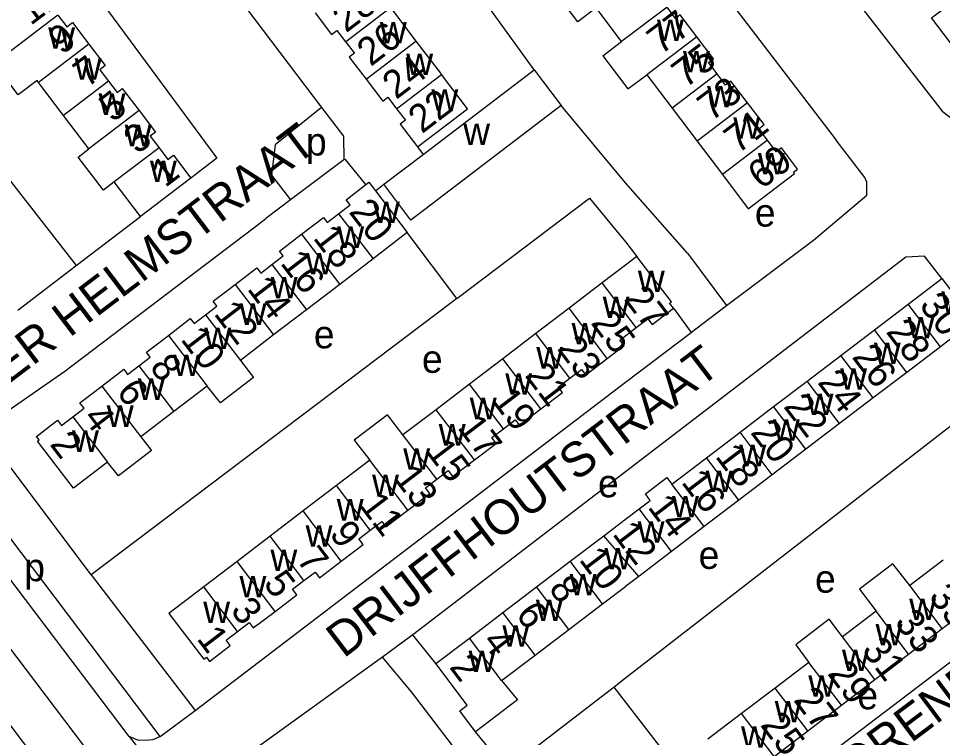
# Model space of a CAD drawing. Extents: x 159294 to 161936, y 384538 to 386517.
# Drawn here: x 160412.8 to 160545.6, y 385575.5 to 385678.8 of the extents above; entities that cross this region are included whole.
import ezdxf

# ---------------------------------------------------------------- set-up
doc = ezdxf.new("R2010")
doc.units = 0
for name, color, linetype in [('BLT_Basislijn', 7, 'Continuous'), ('BLT_Bebouwing', 7, 'Continuous'), ('BLT_Centroide', 7, 'Continuous'), ('BLT_Huisnummer', 7, 'Continuous'), ('BLT_Huisnummer_ tussenligend', 7, 'Continuous'), ('BLT_Onderverdeling_panden', 7, 'Continuous'), ('BLT_Straatnaam', 7, 'Continuous'), ('BLT_Vlakafsluiter', 7, 'Continuous')]:
    doc.layers.add(name, color=color, linetype=linetype)

msp = doc.modelspace()

# ---------------------------------------------------------------- linework, layer by layer
at = {"layer": 'BLT_Basislijn'}
for p, q in [((160425.66, 385706.42), (160456.33, 385665.99)), ((160456.33, 385665.99), (160449.66, 385660.64)), ((160456.33, 385665.99), (160459.45, 385661.88)), ((160459.45, 385661.88), (160459.52, 385658.49)), ((160449.66, 385660.64), (160449.14, 385656.27)), ((160470.09, 385660.36), (160470.9, 385659.26)), ((160459.52, 385658.49), (160451.85, 385652.72)), ((160449.14, 385656.27), (160451.85, 385652.72)), ((160464.06, 385654.02), (160465.25, 385654.97)), ((160451.85, 385652.72), (160448.33, 385650.06)), ((160421.03, 385643.28), (160430.29, 385650.34)), ((160447.84, 385649.69), (160448.33, 385650.06)), ((160475.77, 385638.54), (160468.64, 385648.03)), ((160508.93, 385645.07), (160514.52, 385637.54)), ((160412.66, 385636.9), (160421.03, 385643.28)), ((160506.88, 385637.17), (160509.42, 385633.69)), ((160423.19, 385598.85), (160407.45, 385619.83)), ((160433.13, 385575.64), (160402.33, 385616.36)), ((160428.69, 385575.65), (160400.48, 385612.84)), ((160423.91, 385572.02), (160395.7, 385609.21)), ((160390.64, 385604.74), (160419.63, 385566.66)), ((160423.19, 385598.85), (160438.16, 385579.37)), ((160472.72, 385586.11), (160469.45, 385590.25)), ((160433.13, 385575.64), (160438.16, 385579.37))]:
    msp.add_line(p, q, dxfattribs=at)
for points in [[(160462.6, 385750.62), (160463.37, 385749.24), (160463.73, 385747.8), (160463.54, 385747.15), (160461.25, 385744.68), (160407.86, 385704.37), (160408.02, 385703.72), (160410.79, 385700), (160441.27, 385658.72), (160437.54, 385655.86)], [(160466.65, 385733.68), (160471.23, 385737.23), (160472.38, 385736.43), (160500.69, 385700), (160530.29, 385661.32)], [(160486.88, 385671.4), (160466.25, 385700), (160449.95, 385721.54)], [(160532.44, 385682.31), (160545.5, 385665.46), (160547.76, 385663.73), (160550.07, 385663.68), (160551.02, 385664.1), (160586.59, 385691.5), (160587.15, 385692.07)], [(160381.69, 385691.15), (160383.6, 385688.37), (160385.51, 385688.77), (160385.83, 385688.45), (160421.03, 385643.28)], [(160508.93, 385645.07), (160500, 385655.15), (160490.78, 385666.26)], [(160514.52, 385637.54), (160527, 385646.95), (160534.71, 385653.39), (160534.71, 385655.29), (160534.39, 385655.93), (160530.29, 385661.32)], [(160462.68, 385654.92), (160459.77, 385658.53), (160459.52, 385658.49)], [(160475.77, 385638.54), (160494.85, 385652.96), (160500, 385646.71), (160501.64, 385644.58)], [(160407.45, 385619.83), (160419.41, 385628.13), (160447.84, 385649.69)], [(160545.48, 385641.41), (160542.98, 385644.64), (160540.27, 385644.48), (160500, 385613.68), (160469.45, 385590.25)], [(160475.77, 385638.54), (160475.15, 385638.07), (160423.19, 385598.85)], [(160509.42, 385633.69), (160510.12, 385634.22), (160514.52, 385637.54)], [(160438.16, 385579.37), (160500, 385626.56), (160509.42, 385633.69)], [(160556.46, 385627.73), (160500, 385584), (160498.36, 385582.75)], [(160514.51, 385561.88), (160570.33, 385604.31), (160571.73, 385605.92), (160569.69, 385609.54)], [(160469.45, 385590.25), (160469.12, 385589.99), (160465.07, 385587.05)], [(160465.07, 385587.05), (160464.06, 385586.32), (160443.62, 385571.57)], [(160487.23, 385558.55), (160469.23, 385582.04), (160465.07, 385587.05)], [(160498.36, 385582.75), (160484.46, 385572.06), (160483.32, 385571.65), (160482.22, 385571.7), (160478.46, 385576.33)], [(160507.02, 385571.58), (160500, 385580.61), (160498.36, 385582.75)], [(160433.13, 385575.64), (160432.05, 385575.17), (160430.97, 385575.08), (160429.93, 385575.1), (160428.69, 385575.65)]]:
    msp.add_lwpolyline(points, dxfattribs=at)
at = {"layer": 'BLT_Bebouwing'}
for p, q in [((160466.23, 385680.34), (160469.89, 385675.53)), ((160499.45, 385675.46), (160495.77, 385680.32)), ((160469.89, 385675.53), (160473.55, 385670.72)), ((160496.76, 385673.42), (160499.45, 385675.46)), ((160470.9, 385659.26), (160486.88, 385671.4)), ((160486.88, 385671.4), (160490.78, 385666.26)), ((160419.23, 385664.86), (160415.64, 385669.59)), ((160503.07, 385670.69), (160506.69, 385665.92)), ((160506.69, 385665.92), (160510.29, 385661.17)), ((160422.89, 385660.06), (160419.23, 385664.86)), ((160510.29, 385661.17), (160513.92, 385656.38)), ((160465.25, 385654.97), (160470.9, 385659.26)), ((160513.92, 385656.38), (160517.65, 385651.46)), ((160430.29, 385650.34), (160426.52, 385655.3)), ((160437.54, 385655.86), (160430.29, 385650.34)), ((160464.06, 385654.02), (160468.64, 385648.03)), ((160468.64, 385648.03), (160463.73, 385644.27)), ((160463.73, 385644.27), (160458.93, 385640.59)), ((160501.64, 385644.58), (160500, 385643.33)), ((160500, 385643.33), (160496.66, 385640.79)), ((160458.93, 385640.59), (160454.16, 385636.94)), ((160496.66, 385640.79), (160491.89, 385637.15)), ((160540.63, 385637.73), (160545.48, 385641.41)), ((160545.48, 385641.41), (160550.12, 385635.3)), ((160535.79, 385634.05), (160540.63, 385637.73)), ((160454.16, 385636.94), (160449.43, 385633.32)), ((160491.89, 385637.15), (160487.12, 385633.52)), ((160499.17, 385632.56), (160501.55, 385634.37)), ((160530.96, 385630.38), (160535.79, 385634.05)), ((160449.43, 385633.32), (160444.65, 385629.66)), ((160487.12, 385633.52), (160482.37, 385629.9)), ((160545.27, 385631.62), (160540.44, 385627.95)), ((160482.37, 385629.9), (160477.59, 385626.26)), ((160526.12, 385626.7), (160530.96, 385630.38)), ((160540.44, 385627.95), (160535.6, 385624.27)), ((160439.87, 385625.99), (160435.1, 385622.34)), ((160477.59, 385626.26), (160472.77, 385622.59)), ((160521.29, 385623.03), (160526.12, 385626.7)), ((160516.46, 385619.35), (160521.29, 385623.03)), ((160535.6, 385624.27), (160530.77, 385620.6)), ((160435.1, 385622.34), (160430.33, 385618.69)), ((160472.77, 385622.59), (160468.02, 385618.97)), ((160530.77, 385620.6), (160525.93, 385616.92)), ((160511.62, 385615.68), (160516.46, 385619.35)), ((160525.93, 385616.92), (160521.1, 385613.24)), ((160463.24, 385615.33), (160458.46, 385611.68)), ((160506.65, 385611.89), (160511.62, 385615.68)), ((160521.1, 385613.24), (160516.27, 385609.57)), ((160458.46, 385611.68), (160453.67, 385608.04)), ((160516.27, 385609.57), (160511.33, 385605.82)), ((160453.67, 385608.04), (160448.92, 385604.41)), ((160500, 385606.84), (160501.95, 385608.33)), ((160496.9, 385604.48), (160500, 385606.84)), ((160511.33, 385605.82), (160506.6, 385602.22)), ((160448.92, 385604.41), (160444.17, 385600.8)), ((160492.06, 385600.81), (160496.9, 385604.48)), ((160506.6, 385602.22), (160501.9, 385598.65)), ((160444.17, 385600.8), (160439.38, 385597.15)), ((160487.23, 385597.13), (160492.06, 385600.81)), ((160545.68, 385600.99), (160540.85, 385597.31)), ((160501.9, 385598.65), (160500, 385597.21)), ((160482.39, 385593.46), (160487.23, 385597.13)), ((160496.71, 385594.7), (160500, 385597.21)), ((160491.87, 385591.03), (160496.71, 385594.7)), ((160545.53, 385591.16), (160550.36, 385594.84)), ((160477.56, 385589.78), (160482.39, 385593.46)), ((160536.02, 385593.64), (160531.18, 385589.96)), ((160540.69, 385587.49), (160545.53, 385591.16)), ((160472.72, 385586.11), (160477.56, 385589.78)), ((160487.04, 385587.35), (160491.87, 385591.03)), ((160482.2, 385583.67), (160487.04, 385587.35)), ((160535.86, 385583.81), (160540.69, 385587.49)), ((160526.35, 385586.28), (160521.52, 385582.61)), ((160531.03, 385580.13), (160535.86, 385583.81)), ((160521.52, 385582.61), (160516.68, 385578.93)), ((160526.19, 385576.46), (160531.03, 385580.13)), ((160516.68, 385578.93), (160511.85, 385575.25)), ((160521.36, 385572.78), (160526.19, 385576.46))]:
    msp.add_line(p, q, dxfattribs=at)
for points in [[(160495.77, 385680.32), (160493.17, 385678.28), (160489.54, 385683.06), (160492.15, 385685.1)], [(160555.32, 385673.96), (160550.49, 385670.3), (160545.8, 385676.48), (160543.98, 385678.89), (160548.94, 385682.64), (160550.64, 385680.15)], [(160510.27, 385676.15), (160507.87, 385679.3), (160507.2, 385678.8), (160505.98, 385680.41)], [(160418.42, 385679.28), (160419.72, 385677.58), (160420.52, 385678.19), (160422.88, 385675.1)], [(160455.38, 385679.58), (160457.74, 385676.47), (160458.53, 385677.07), (160459.78, 385675.42)], [(160513.16, 385670.82), (160511.94, 385672.44), (160512.66, 385672.99), (160510.27, 385676.15)], [(160422.88, 385675.1), (160425.23, 385672.01), (160424.45, 385671.41), (160425.69, 385669.78)], [(160459.78, 385675.42), (160461.03, 385673.78), (160460.3, 385673.23), (160462.71, 385670.07)], [(160415.64, 385669.59), (160415.43, 385669.86), (160412.72, 385667.8), (160409.27, 385672.32)], [(160496.76, 385673.42), (160500.36, 385668.67), (160503.07, 385670.69)], [(160517.54, 385666.66), (160515.16, 385669.8), (160514.38, 385669.21), (160513.16, 385670.82)], [(160425.69, 385669.78), (160426.93, 385668.15), (160427.68, 385668.72), (160430.09, 385665.55)], [(160462.71, 385670.07), (160465.12, 385666.91), (160465.84, 385667.46), (160467.1, 385665.81)], [(160470.09, 385660.36), (160474.07, 385663.38), (160477.28, 385665.82), (160473.55, 385670.72)], [(160430.09, 385665.55), (160432.44, 385662.46), (160431.68, 385661.88), (160432.96, 385660.2)], [(160490.78, 385666.26), (160469.15, 385649.83), (160465.25, 385654.97)], [(160467.1, 385665.81), (160468.36, 385664.16), (160467.62, 385663.6), (160470.09, 385660.36)], [(160520.4, 385661.3), (160519.15, 385662.95), (160519.92, 385663.53), (160517.54, 385666.66)], [(160432.96, 385660.2), (160434.24, 385658.52), (160435.04, 385659.13), (160437.54, 385655.86)], [(160524.74, 385657.14), (160522.41, 385660.22), (160521.65, 385659.65), (160520.4, 385661.3)], [(160426.52, 385655.3), (160424.97, 385654.11), (160421.34, 385658.88), (160422.89, 385660.06)], [(160517.65, 385651.46), (160524.3, 385656.5), (160524.16, 385656.69), (160524.74, 385657.14)], [(160458.77, 385650.74), (160460.41, 385651.99), (160459.84, 385652.74), (160462.68, 385654.92)], [(160462.68, 385654.92), (160463.12, 385655.25), (160464.06, 385654.02)], [(160453.42, 385647.79), (160456.58, 385650.21), (160457.14, 385649.49), (160458.77, 385650.74)], [(160449.19, 385643.44), (160450.8, 385644.67), (160450.26, 385645.37), (160453.42, 385647.79)], [(160506.88, 385637.17), (160506.35, 385637.87), (160506.6, 385638.06), (160501.64, 385644.58)], [(160443.88, 385640.55), (160447.01, 385642.95), (160447.58, 385642.21), (160449.19, 385643.44)], [(160439.64, 385636.21), (160441.28, 385637.47), (160440.75, 385638.16), (160443.88, 385640.55)], [(160501.55, 385634.37), (160503.23, 385635.64), (160503.84, 385634.84), (160506.88, 385637.17)], [(160434.3, 385633.26), (160437.44, 385635.67), (160437.99, 385634.95), (160439.64, 385636.21)], [(160550.12, 385635.3), (160546.14, 385632.28), (160545.27, 385631.62)], [(160430.07, 385628.9), (160431.7, 385630.15), (160431.16, 385630.85), (160434.3, 385633.26)], [(160497.38, 385629.95), (160499.8, 385631.79), (160499.17, 385632.56)], [(160444.65, 385629.66), (160446.54, 385627.21), (160441.78, 385623.56), (160439.87, 385625.99)], [(160492, 385627.11), (160493.67, 385628.38), (160494.28, 385627.58), (160497.38, 385629.95)], [(160424.74, 385625.99), (160427.88, 385628.4), (160428.45, 385627.65), (160430.07, 385628.9)], [(160487.85, 385622.71), (160490.93, 385625.06), (160490.34, 385625.84), (160492, 385627.11)], [(160420.58, 385621.55), (160422.2, 385622.8), (160421.6, 385623.59), (160424.74, 385625.99)], [(160468.02, 385618.97), (160465.79, 385621.85), (160461.02, 385618.21), (160463.24, 385615.33)], [(160482.46, 385619.86), (160484.16, 385621.15), (160484.76, 385620.36), (160487.85, 385622.71)], [(160425.56, 385615.04), (160420.68, 385611.3), (160415.49, 385618.07), (160415.72, 385618.24), (160415.33, 385618.76), (160418.37, 385621.08), (160418.95, 385620.31), (160420.58, 385621.55)], [(160478.28, 385615.37), (160481.4, 385617.74), (160480.77, 385618.57), (160482.46, 385619.86)], [(160430.33, 385618.69), (160431.9, 385616.72), (160427.14, 385613.07), (160425.56, 385615.04)], [(160472.89, 385612.59), (160474.52, 385613.83), (160475.16, 385612.99), (160478.28, 385615.37)], [(160468.71, 385608.15), (160471.86, 385610.55), (160471.25, 385611.34), (160472.89, 385612.59)], [(160501.95, 385608.33), (160503.57, 385609.56), (160502.86, 385610.5), (160505.93, 385612.83), (160506.65, 385611.89)], [(160463.32, 385605.29), (160464.96, 385606.55), (160465.57, 385605.76), (160468.71, 385608.15)], [(160459.15, 385600.84), (160462.29, 385603.24), (160461.68, 385604.04), (160463.32, 385605.29)], [(160453.77, 385598.05), (160455.39, 385599.27), (160456.01, 385598.45), (160459.15, 385600.84)], [(160540.85, 385597.31), (160538.42, 385600.45), (160533.61, 385596.79), (160536.02, 385593.64)], [(160449.64, 385593.62), (160452.78, 385596.01), (160452.16, 385596.82), (160453.77, 385598.05)], [(160439.38, 385597.15), (160434.36, 385593.32), (160439.38, 385586.73), (160439.76, 385587.02), (160440.2, 385586.44), (160443.19, 385588.72), (160442.61, 385589.48), (160444.26, 385590.74)], [(160444.26, 385590.74), (160445.92, 385592), (160446.51, 385591.23), (160449.64, 385593.62)], [(160531.18, 385589.96), (160529.29, 385592.49), (160524.48, 385588.83), (160526.35, 385586.28)], [(160478.46, 385576.33), (160476.18, 385579.32), (160477.26, 385580.14), (160472.72, 385586.11)], [(160482.2, 385583.67), (160484.5, 385580.92), (160478.46, 385576.33)]]:
    msp.add_lwpolyline(points, dxfattribs=at)
at = {"layer": 'BLT_Onderverdeling_panden'}
for p, q in [((160459.78, 385675.42), (160466.23, 385680.34)), ((160505.98, 385680.41), (160499.45, 385675.46)), ((160418.42, 385679.28), (160409.27, 385672.32)), ((160510.27, 385676.15), (160503.07, 385670.69)), ((160422.88, 385675.1), (160415.64, 385669.59)), ((160462.71, 385670.07), (160469.89, 385675.53)), ((160513.16, 385670.82), (160506.69, 385665.92)), ((160425.69, 385669.78), (160419.23, 385664.86)), ((160467.1, 385665.81), (160473.55, 385670.72)), ((160430.09, 385665.55), (160422.89, 385660.06)), ((160517.54, 385666.66), (160510.29, 385661.17)), ((160432.96, 385660.2), (160426.52, 385655.3)), ((160520.4, 385661.3), (160513.92, 385656.38)), ((160458.77, 385650.74), (160463.73, 385644.27)), ((160453.42, 385647.79), (160458.93, 385640.59)), ((160449.19, 385643.44), (160454.16, 385636.94)), ((160443.88, 385640.55), (160449.43, 385633.32)), ((160501.55, 385634.37), (160496.66, 385640.79)), ((160545.27, 385631.62), (160540.63, 385637.73)), ((160497.38, 385629.95), (160491.89, 385637.15)), ((160439.64, 385636.21), (160444.65, 385629.66)), ((160540.44, 385627.95), (160535.79, 385634.05)), ((160434.3, 385633.26), (160439.87, 385625.99)), ((160492, 385627.11), (160487.12, 385633.52)), ((160487.85, 385622.71), (160482.37, 385629.9)), ((160535.6, 385624.27), (160530.96, 385630.38)), ((160430.07, 385628.9), (160435.1, 385622.34)), ((160424.74, 385625.99), (160430.33, 385618.69)), ((160482.46, 385619.86), (160477.59, 385626.26)), ((160530.77, 385620.6), (160526.12, 385626.7)), ((160525.93, 385616.92), (160521.29, 385623.03)), ((160478.28, 385615.37), (160472.77, 385622.59)), ((160420.58, 385621.55), (160425.56, 385615.04)), ((160521.1, 385613.24), (160516.46, 385619.35)), ((160472.89, 385612.59), (160468.02, 385618.97)), ((160468.71, 385608.15), (160463.24, 385615.33)), ((160516.27, 385609.57), (160511.62, 385615.68)), ((160463.32, 385605.29), (160458.46, 385611.68)), ((160511.33, 385605.82), (160506.65, 385611.89)), ((160459.15, 385600.84), (160453.67, 385608.04)), ((160506.6, 385602.22), (160501.95, 385608.33)), ((160453.77, 385598.05), (160448.92, 385604.41)), ((160501.9, 385598.65), (160496.9, 385604.48)), ((160449.64, 385593.62), (160444.17, 385600.8)), ((160496.71, 385594.7), (160492.06, 385600.81)), ((160444.26, 385590.74), (160439.38, 385597.15)), ((160491.87, 385591.03), (160487.23, 385597.13)), ((160545.53, 385591.16), (160540.85, 385597.31)), ((160487.04, 385587.35), (160482.39, 385593.46)), ((160540.69, 385587.49), (160536.02, 385593.64)), ((160482.2, 385583.67), (160477.56, 385589.78)), ((160535.86, 385583.81), (160531.18, 385589.96)), ((160531.03, 385580.13), (160526.35, 385586.28)), ((160526.19, 385576.46), (160521.52, 385582.61)), ((160521.36, 385572.78), (160516.68, 385578.93))]:
    msp.add_line(p, q, dxfattribs=at)
at = {"layer": 'BLT_Vlakafsluiter'}
msp.add_line((160428.69, 385575.65), (160437.34, 385564.52), dxfattribs=at)

# ---------------------------------------------------------------- texts
at = {"layer": 'BLT_Centroide'}
for s, p in [('w', (160417.03, 385674.44)), ('w', (160464.7, 385675.19)), ('w', (160504.52, 385675.56)), ('w', (160468.49, 385670.66)), ('w', (160508.26, 385671.03)), ('w', (160420.84, 385669.97)), ('w', (160472.1, 385665.53)), ('w', (160511.73, 385666)), ('w', (160424.27, 385664.94)), ('w', (160515.49, 385661.53)), ('w', (160428.03, 385660.44)), ('w', (160476.68, 385660.62)), ('p', (160454.08, 385659.1)), ('w', (160519.03, 385656.38)), ('w', (160431.65, 385655.28)), ('w', (160463.7, 385649.38)), ('e', (160518.59, 385648.89)), ('w', (160458.58, 385645.83)), ('w', (160454.06, 385642.02)), ('w', (160449.02, 385638.58)), ('w', (160501.78, 385639.47)), ('w', (160545.38, 385636.52)), ('w', (160444.53, 385634.77)), ('w', (160496.72, 385635.77)), ('w', (160492.25, 385631.98)), ('w', (160540.53, 385632.84)), ('w', (160439.47, 385631.3)), ('e', (160455.21, 385631.4)), ('e', (160470.75, 385627.88)), ('w', (160487.19, 385628.5)), ('w', (160535.7, 385629.16)), ('w', (160434.97, 385627.44)), ('w', (160530.86, 385625.48)), ('w', (160429.92, 385624)), ('w', (160482.72, 385624.75)), ('w', (160477.62, 385621.22)), ('w', (160526.03, 385621.81)), ('w', (160425.45, 385620.12)), ('w', (160473.16, 385617.44)), ('w', (160521.19, 385618.14)), ('w', (160420.45, 385616.53)), ('w', (160468.06, 385613.95)), ('w', (160516.36, 385614.47)), ('w', (160511.53, 385610.78)), ('w', (160463.58, 385610.19)), ('e', (160496.05, 385610)), ('w', (160458.5, 385606.67)), ('w', (160506.69, 385607.11)), ('w', (160454.03, 385602.91)), ('w', (160501.75, 385603.48)), ('w', (160448.97, 385599.42)), ('w', (160496.98, 385599.64)), ('e', (160510.51, 385599.72)), ('p', (160413.59, 385597.95)), ('e', (160527.24, 385596.3)), ('w', (160444.52, 385595.64)), ('w', (160491.97, 385595.92)), ('w', (160487.12, 385592.25)), ('w', (160540.77, 385592.39)), ('w', (160439.31, 385591.95)), ('w', (160482.3, 385588.56)), ('w', (160535.94, 385588.72)), ('w', (160477.45, 385584.89)), ('w', (160531.11, 385585.05)), ('w', (160526.27, 385581.38)), ('e', (160533.33, 385579.55)), ('w', (160521.44, 385577.69)), ('w', (160516.61, 385574.02))]:
    msp.add_text(s, height=4, dxfattribs=at).set_placement(p)
at = {"layer": 'BLT_Huisnummer'}
for s, rotation, p in [('77', 37.1638, (160505.06, 385673.46)), ('9', 37.2851, (160419.01, 385673.46)), ('26', 37.264, (160463.38, 385671.79)), ('73', 37.1638, (160512.31, 385663.91)), ('5', 37.2851, (160426.3, 385663.76)), ('22', 37.264, (160470.74, 385662.15)), ('69', 37.1638, (160519.54, 385654.12)), ('1', 37.2851, (160433.84, 385654.4)), ('20', 307.4424, (160460.14, 385650.97)), ('14', 307.4424, (160445.52, 385639.92)), ('27', 307.3, (160499.67, 385638.47)), ('30', 307.2403, (160542.11, 385637.55)), ('10', 307.4424, (160435.96, 385632.67)), ('26', 307.2403, (160532.44, 385630.14)), ('21', 307.3, (160485.43, 385627.49)), ('6', 307.4424, (160426.72, 385625.12)), ('22', 307.2403, (160522.61, 385623.03)), ('17', 307.3, (160475.74, 385620.01)), ('2', 307.4424, (160417.16, 385617.6)), ('18', 307.2403, (160512.8, 385615.85)), ('13', 307.3, (160466.53, 385612.78)), ('14', 307.2403, (160503.09, 385608.57)), ('9', 307.3, (160457.33, 385604.74)), ('10', 307.2403, (160493.23, 385601.02)), ('5', 307.3, (160447.85, 385597.59)), ('6', 307.2403, (160484.11, 385593.13)), ('33', 307.2618, (160538.55, 385592.01)), ('1', 307.3, (160438.27, 385589.68)), ('2', 307.2403, (160474.59, 385585.59)), ('29', 307.2618, (160528.92, 385584.67)), ('25', 307.2618, (160519.27, 385577.28))]:
    msp.add_text(s, height=4, rotation=rotation, dxfattribs=at).set_placement(p)
at = {"layer": 'BLT_Huisnummer_ tussenligend'}
for s, rotation, p in [('11', 37.2851, (160414.51, 385677.68)), ('28', 37.264, (160459.83, 385676.63)), ('75', 37.1638, (160508.61, 385668.68)), ('7', 37.2851, (160422.6, 385668.73)), ('24', 37.264, (160467.03, 385667.05)), ('71', 37.1638, (160516.13, 385659.24)), ('3', 37.2851, (160429.85, 385659.18)), ('18', 307.4424, (160454.99, 385647.24)), ('16', 307.4424, (160450.28, 385643.62)), ('12', 307.4424, (160440.73, 385636.36)), ('25', 307.3, (160494.91, 385635.03)), ('28', 307.2403, (160537.33, 385633.76)), ('23', 307.3, (160490.07, 385631.33)), ('8', 307.4424, (160431.5, 385628.67)), ('24', 307.2403, (160527.49, 385626.49)), ('19', 307.3, (160480.65, 385623.92)), ('4', 307.4424, (160421.92, 385621.38)), ('20', 307.2403, (160517.86, 385619.29)), ('15', 307.3, (160471.23, 385616.55)), ('16', 307.2403, (160507.92, 385612.15)), ('11', 307.3, (160461.63, 385608.83)), ('12', 307.2403, (160498.02, 385604.72)), ('7', 307.3, (160452.61, 385601.02)), ('8', 307.2403, (160488.85, 385596.86)), ('35', 307.2618, (160543.46, 385595.72)), ('3', 307.3, (160443.12, 385593.74)), ('4', 307.2403, (160479.29, 385589.24)), ('31', 307.2618, (160533.83, 385588.02)), ('27', 307.2618, (160524.04, 385580.86))]:
    msp.add_text(s, height=4, rotation=rotation, dxfattribs=at).set_placement(p)
at = {"layer": 'BLT_Straatnaam'}
for s, rotation, p in [('VAN DER HELMSTRAAT', 37.2203, (160394.95, 385613.77)), ('DRIJFFHOUTSTRAAT', 37.2201, (160459.49, 385586.8)), ('VAN NORENBURCHSTRAAT', 36.8707, (160516.67, 385556.35))]:
    msp.add_text(s, height=5, rotation=rotation, dxfattribs=at).set_placement(p)

doc.saveas('drawing.dxf')
